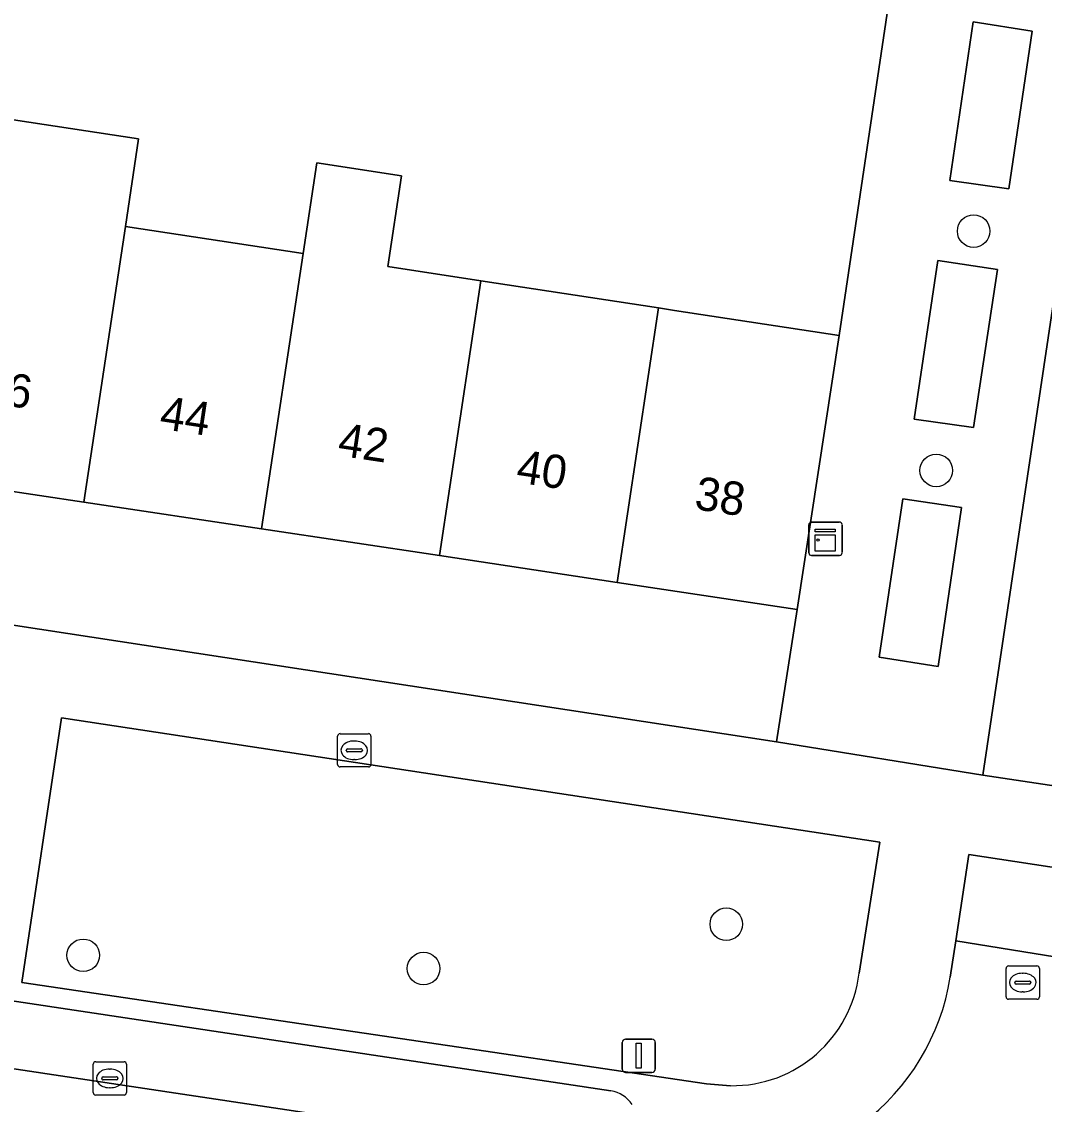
# Model space of a CAD drawing. Extents: x 163008 to 163854, y 382777 to 383982.
# Drawn here: x 163578.61 to 163609.33, y 383213.27 to 383245.8 of the extents above; entities that cross this region are included whole.
import ezdxf

# ---------------------------------------------------------------- set-up
doc = ezdxf.new("R2010")
doc.units = 0
for name, color, linetype in [('IMGEO_Boom', 7, 'Continuous'), ('IMGEO_Brandkraan', 7, 'Continuous'), ('IMGEO_Erf', 7, 'Continuous'), ('IMGEO_Groenvoorziening', 7, 'Continuous'), ('IMGEO_Kast', 7, 'Continuous'), ('IMGEO_Kolk', 7, 'Continuous'), ('IMGEO_Lichtmast', 7, 'Continuous'), ('IMGEO_Muur', 7, 'Continuous'), ('IMGEO_Pand', 7, 'Continuous'), ('IMGEO_Pand_nummerreeks', 7, 'Continuous'), ('IMGEO_Parkeervlak_open', 7, 'Continuous'), ('IMGEO_Rijbaan_lokaal_gesloten', 7, 'Continuous'), ('IMGEO_Rijbaan_lokaal_open', 7, 'Continuous'), ('IMGEO_Rioolput', 7, 'Continuous'), ('IMGEO_Voetpad_open', 7, 'Continuous')]:
    doc.layers.add(name, color=color, linetype=linetype)

msp = doc.modelspace()

# ---------------------------------------------------------------- linework, layer by layer
at = {"layer": 'IMGEO_Boom'}
for centre in [(163607.204, 383239.508), (163606.082, 383232.318), (163599.776, 383218.685), (163580.462, 383217.75), (163590.684, 383217.351)]:
    msp.add_circle(centre, 0.489, dxfattribs=at)
at = {"layer": 'IMGEO_Brandkraan'}
for p, q in [((163588.102, 383223.483), (163588.102, 383224.335)), ((163588.177, 383224.409), (163589.029, 383224.409)), ((163589.103, 383224.335), (163589.103, 383223.483)), ((163588.59, 383224.189), (163588.615, 383224.189)), ((163588.361, 383223.903), (163588.361, 383223.915)), ((163588.799, 383223.866), (163588.401, 383223.866)), ((163588.404, 383223.952), (163588.802, 383223.952)), ((163588.845, 383223.915), (163588.845, 383223.903)), ((163589.029, 383223.409), (163588.177, 383223.409)), ((163588.613, 383223.629), (163588.588, 383223.629))]:
    msp.add_line(p, q, dxfattribs=at)
for points in [[(163588.102, 383223.483), (163588.102, 383224.335)], [(163588.177, 383224.409), (163589.029, 383224.409)], [(163589.103, 383224.335), (163589.103, 383223.483)], [(163589.029, 383223.409), (163588.177, 383223.409)]]:
    msp.add_lwpolyline(points, dxfattribs=at)
for centre, radius, start, end in [((163588.179, 383224.333), 0.0765, 91.552, 178.448), ((163588.179, 383224.333), 0.0765, 91.552, 178.448), ((163589.027, 383224.333), 0.0765, 1.552, 88.448), ((163589.027, 383224.333), 0.0765, 1.552, 88.448), ((163588.401, 383223.912), 0.0403, 85.8775, 175.7526), ((163588.398, 383223.902), 0.0366, 178.938, 274.7102), ((163588.802, 383223.909), 0.043, 264.8664, 352.4533), ((163588.806, 383223.914), 0.0386, 1.7309, 96.639), ((163588.179, 383223.485), 0.0765, 181.552, 268.448), ((163588.179, 383223.485), 0.0765, 181.552, 268.448), ((163589.027, 383223.485), 0.0765, 271.552, 358.448), ((163589.027, 383223.485), 0.0765, 271.552, 358.448)]:
    msp.add_arc(centre, radius, start, end, dxfattribs=at)
for centre, major_axis, ratio, start_param, end_param in [((163588.589, 383223.909), (-0.387, 0.002), 0.722429, 4.712389, 7.853982), ((163588.614, 383223.909), (-0.39, 0.002), 0.717154, 1.570796, 4.712389)]:
    msp.add_ellipse(centre, major_axis=major_axis, ratio=ratio, start_param=start_param, end_param=end_param, dxfattribs=at)
at = {"layer": 'IMGEO_Erf'}
msp.add_lwpolyline([(163555.832, 383249.496), (163554.992, 383243.736), (163559.935, 383242.98), (163560.373, 383242.913), (163565.712, 383242.097), (163571.05, 383241.28), (163576.388, 383240.464), (163576.774, 383243.089), (163582.123, 383242.284), (163581.726, 383239.648), (163587.063, 383238.831), (163587.473, 383241.556), (163590.025, 383241.172), (163589.614, 383238.441), (163592.401, 383238.015), (163597.739, 383237.199), (163598.222, 383237.125), (163603.164, 383236.369), (163604.845, 383247.675)], dxfattribs=at)
msp.add_lwpolyline([(163553.141, 383231.523), (163601.286, 383224.16), (163601.906, 383228.141), (163596.498, 383228.955), (163591.158, 383229.759), (163585.818, 383230.562), (163580.479, 383231.366), (163575.139, 383232.17), (163569.799, 383232.973), (163564.459, 383233.777), (163559.119, 383234.581), (163553.717, 383235.394)], close=True, dxfattribs=at)
at = {"layer": 'IMGEO_Groenvoorziening'}
msp.add_lwpolyline([(163603.762, 383217.217), (163604.384, 383221.146), (163579.809, 383224.886), (163578.619, 383216.935), (163599.182, 383213.891), (163599.899, 383213.833)], dxfattribs=at)
msp.add_arc((163599.96, 383217.661), 3.828, 269.0921, 353.3448, dxfattribs=at)
at = {"layer": 'IMGEO_Kast'}
for p, q in [((163602.252, 383229.838), (163602.252, 383230.679)), ((163602.252, 383230.679), (163602.252, 383229.838)), ((163602.327, 383230.763), (163603.168, 383230.763)), ((163603.168, 383230.763), (163602.327, 383230.763)), ((163603.252, 383230.688), (163603.252, 383229.847)), ((163603.252, 383229.847), (163603.252, 383230.688)), ((163603.177, 383229.763), (163602.336, 383229.763)), ((163602.336, 383229.763), (163603.177, 383229.763))]:
    msp.add_line(p, q, dxfattribs=at)
for points in [[(163602.447, 383230.553), (163603.047, 383230.553), (163603.047, 383230.468), (163602.447, 383230.468), (163602.447, 383230.553)], [(163602.447, 383230.378), (163603.047, 383230.378), (163603.047, 383229.889), (163602.447, 383229.889), (163602.447, 383230.378)]]:
    msp.add_lwpolyline(points, dxfattribs=at)
msp.add_circle((163602.531, 383230.227), 0.0377, dxfattribs=at)
for centre, start, end in [((163602.33, 383230.685), 92.4484, 184.2845), ((163602.33, 383230.685), 92.4484, 184.2845), ((163603.174, 383230.685), 2.4484, 94.2845), ((163603.174, 383230.685), 2.4484, 94.2845), ((163602.33, 383229.841), 182.4484, 274.2845), ((163602.33, 383229.841), 182.4484, 274.2845), ((163603.174, 383229.841), 272.4484, 4.2845), ((163603.174, 383229.841), 272.4484, 4.2845)]:
    msp.add_arc(centre, 0.0779, start, end, dxfattribs=at)
at = {"layer": 'IMGEO_Kolk'}
for p, q in [((163580.76, 383213.627), (163580.76, 383214.479)), ((163580.835, 383214.553), (163581.687, 383214.553)), ((163581.248, 383214.333), (163581.273, 383214.333)), ((163581.761, 383214.479), (163581.761, 383213.627)), ((163581.019, 383214.047), (163581.019, 383214.059)), ((163581.457, 383214.01), (163581.059, 383214.01)), ((163581.062, 383214.096), (163581.46, 383214.096)), ((163581.503, 383214.059), (163581.503, 383214.047)), ((163581.271, 383213.773), (163581.246, 383213.773)), ((163581.687, 383213.553), (163580.835, 383213.553))]:
    msp.add_line(p, q, dxfattribs=at)
for points in [[(163580.76, 383213.627), (163580.76, 383214.479)], [(163580.835, 383214.553), (163581.687, 383214.553)], [(163581.761, 383214.479), (163581.761, 383213.627)], [(163581.687, 383213.553), (163580.835, 383213.553)]]:
    msp.add_lwpolyline(points, dxfattribs=at)
for centre, radius, start, end in [((163580.837, 383214.477), 0.0765, 91.552, 178.448), ((163580.837, 383214.477), 0.0765, 91.552, 178.448), ((163581.685, 383214.477), 0.0765, 1.552, 88.448), ((163581.685, 383214.477), 0.0765, 1.552, 88.448), ((163581.059, 383214.056), 0.0403, 85.8775, 175.7526), ((163581.056, 383214.046), 0.0366, 178.938, 274.7102), ((163581.46, 383214.053), 0.043, 264.8664, 352.4533), ((163581.464, 383214.058), 0.0386, 1.7309, 96.639), ((163580.837, 383213.629), 0.0765, 181.552, 268.448), ((163580.837, 383213.629), 0.0765, 181.552, 268.448), ((163581.685, 383213.629), 0.0765, 271.552, 358.448), ((163581.685, 383213.629), 0.0765, 271.552, 358.448)]:
    msp.add_arc(centre, radius, start, end, dxfattribs=at)
for centre, major_axis, ratio, start_param, end_param in [((163581.247, 383214.053), (-0.387, 0.002), 0.722429, 4.712389, 7.853982), ((163581.272, 383214.053), (-0.39, 0.002), 0.717154, 1.570796, 4.712389)]:
    msp.add_ellipse(centre, major_axis=major_axis, ratio=ratio, start_param=start_param, end_param=end_param, dxfattribs=at)
at = {"layer": 'IMGEO_Lichtmast'}
for p, q in [((163596.752, 383215.234), (163597.542, 383215.234)), ((163597.542, 383215.234), (163596.752, 383215.234)), ((163596.652, 383214.334), (163596.652, 383215.134)), ((163596.652, 383215.134), (163596.652, 383214.334)), ((163597.642, 383215.134), (163597.642, 383214.334)), ((163597.642, 383214.334), (163597.642, 383215.134)), ((163597.542, 383214.234), (163596.752, 383214.234)), ((163596.752, 383214.234), (163597.542, 383214.234))]:
    msp.add_line(p, q, dxfattribs=at)
msp.add_lwpolyline([(163597.072, 383215.109), (163597.222, 383215.109), (163597.222, 383214.359), (163597.072, 383214.359), (163597.072, 383215.109)], dxfattribs=at)
for centre, start, end in [((163596.752, 383215.134), 90, 180), ((163596.752, 383215.134), 90, 180), ((163597.542, 383215.134), 0, 90), ((163597.542, 383215.134), 360, 90), ((163596.752, 383214.334), 180, 270), ((163596.752, 383214.334), 180, 270), ((163597.542, 383214.334), 270, 0), ((163597.542, 383214.334), 270, 0)]:
    msp.add_arc(centre, 0.1, start, end, dxfattribs=at)
at = {"layer": 'IMGEO_Muur'}
msp.add_lwpolyline([(163603.164, 383236.369), (163604.845, 383247.675)], dxfattribs=at)
at = {"layer": 'IMGEO_Pand'}
for points in [[(163581.726, 383239.648), (163582.123, 383242.284), (163576.774, 383243.089), (163576.388, 383240.464), (163575.139, 383232.17), (163580.479, 383231.366)], [(163587.063, 383238.831), (163585.818, 383230.562), (163591.158, 383229.759), (163592.401, 383238.015), (163589.614, 383238.441), (163590.025, 383241.172), (163587.473, 383241.556)], [(163587.063, 383238.831), (163581.726, 383239.648), (163580.479, 383231.366), (163585.818, 383230.562)], [(163596.498, 383228.955), (163597.739, 383237.199), (163592.401, 383238.015), (163591.158, 383229.759)], [(163596.498, 383228.955), (163601.906, 383228.141), (163603.164, 383236.369), (163598.222, 383237.125), (163597.739, 383237.199)]]:
    msp.add_lwpolyline(points, close=True, dxfattribs=at)
at = {"layer": 'IMGEO_Parkeervlak_open'}
for points in [[(163608.265, 383240.776), (163608.962, 383245.518), (163607.192, 383245.792), (163606.49, 383241.023)], [(163607.195, 383233.61), (163607.921, 383238.358), (163606.126, 383238.625), (163605.417, 383233.862)], [(163606.139, 383226.43), (163606.843, 383231.208), (163605.075, 383231.468), (163604.365, 383226.703)]]:
    msp.add_lwpolyline(points, close=True, dxfattribs=at)
for points in [[(163596.308, 383213.676), (163554.672, 383219.939)], [(163551.582, 383218.367), (163599.104, 383211.221)]]:
    msp.add_lwpolyline(points, dxfattribs=at)
msp.add_arc((163596.173, 383212.752), 0.933, 33.9028, 81.701, dxfattribs=at)
at = {"layer": 'IMGEO_Rijbaan_lokaal_gesloten'}
msp.add_lwpolyline([(163551.317, 383216.605), (163599.147, 383209.408), (163599.431, 383211.199), (163599.104, 383211.221), (163551.582, 383218.367)], close=True, dxfattribs=at)
at = {"layer": 'IMGEO_Rijbaan_lokaal_open'}
msp.add_lwpolyline([(163610.88, 383222.652), (163614.476, 383246.512), (163611.042, 383247.039), (163607.483, 383223.163)], close=True, dxfattribs=at)
msp.add_lwpolyline([(163609.834, 383216.499), (163610.014, 383217.649), (163606.665, 383218.189), (163606.501, 383217.095)], dxfattribs=at)
msp.add_arc((163599.715, 383218.176), 6.872, 306.9552, 350.9455, dxfattribs=at)
at = {"layer": 'IMGEO_Rioolput'}
for p, q in [((163608.178, 383216.505), (163608.178, 383217.357)), ((163608.253, 383217.431), (163609.105, 383217.431)), ((163608.666, 383217.211), (163608.691, 383217.211)), ((163609.179, 383217.357), (163609.179, 383216.505)), ((163608.437, 383216.925), (163608.437, 383216.937)), ((163608.875, 383216.888), (163608.477, 383216.888)), ((163608.48, 383216.974), (163608.878, 383216.974)), ((163608.921, 383216.937), (163608.921, 383216.925)), ((163608.689, 383216.651), (163608.664, 383216.651)), ((163609.105, 383216.431), (163608.253, 383216.431))]:
    msp.add_line(p, q, dxfattribs=at)
for points in [[(163608.178, 383216.505), (163608.178, 383217.357)], [(163608.253, 383217.431), (163609.105, 383217.431)], [(163609.179, 383217.357), (163609.179, 383216.505)], [(163609.105, 383216.431), (163608.253, 383216.431)]]:
    msp.add_lwpolyline(points, dxfattribs=at)
for centre, radius, start, end in [((163608.255, 383217.355), 0.0765, 91.552, 178.448), ((163608.255, 383217.355), 0.0765, 91.552, 178.448), ((163609.103, 383217.355), 0.0765, 1.552, 88.448), ((163609.103, 383217.355), 0.0765, 1.552, 88.448), ((163608.477, 383216.934), 0.0403, 85.8775, 175.7526), ((163608.474, 383216.924), 0.0366, 178.938, 274.7102), ((163608.878, 383216.931), 0.043, 264.8664, 352.4533), ((163608.882, 383216.936), 0.0386, 1.7309, 96.639), ((163608.255, 383216.507), 0.0765, 181.552, 268.448), ((163608.255, 383216.507), 0.0765, 181.552, 268.448), ((163609.103, 383216.507), 0.0765, 271.552, 358.448), ((163609.103, 383216.507), 0.0765, 271.552, 358.448)]:
    msp.add_arc(centre, radius, start, end, dxfattribs=at)
for centre, major_axis, ratio, start_param, end_param in [((163608.665, 383216.931), (-0.387, 0.002), 0.722429, 4.712389, 7.853982), ((163608.69, 383216.931), (-0.39, 0.002), 0.717154, 1.570796, 4.712389)]:
    msp.add_ellipse(centre, major_axis=major_axis, ratio=ratio, start_param=start_param, end_param=end_param, dxfattribs=at)
at = {"layer": 'IMGEO_Voetpad_open'}
for points in [[(163618.941, 383233.649), (163620.614, 383244.998), (163620.668, 383245.357), (163620.284, 383245.414), (163620.803, 383248.742), (163618.346, 383249.06), (163614.854, 383249.541), (163611.826, 383250), (163611.443, 383250.058), (163608.303, 383250.604), (163605.388, 383251.086), (163605.18, 383250), (163604.845, 383247.675), (163603.164, 383236.369), (163601.906, 383228.141), (163601.286, 383224.16), (163607.483, 383223.163), (163611.042, 383247.039), (163614.476, 383246.512), (163610.88, 383222.652), (163617.111, 383221.572), (163617.75, 383225.735)], [(163608.265, 383240.776), (163606.49, 383241.023), (163607.192, 383245.792), (163608.962, 383245.518)], [(163607.195, 383233.61), (163605.417, 383233.862), (163606.126, 383238.625), (163607.921, 383238.358)], [(163606.139, 383226.43), (163604.365, 383226.703), (163605.075, 383231.468), (163606.843, 383231.208)], [(163610.417, 383220.269), (163607.06, 383220.78), (163606.665, 383218.189), (163610.014, 383217.649)]]:
    msp.add_lwpolyline(points, close=True, dxfattribs=at)
for points in [[(163610.88, 383222.652), (163607.483, 383223.163), (163601.286, 383224.16), (163553.141, 383231.523), (163553.112, 383231.333), (163546.124, 383232.387), (163542.594, 383232.919), (163542.114, 383230.548), (163545.619, 383230.024), (163544.84, 383224.686)], [(163599.899, 383213.833), (163599.182, 383213.891), (163578.619, 383216.935), (163579.809, 383224.886), (163604.384, 383221.146)], [(163606.501, 383217.095), (163606.665, 383218.189), (163607.06, 383220.78), (163610.417, 383220.269), (163610.88, 383222.652)], [(163604.384, 383221.146), (163603.762, 383217.217)], [(163554.672, 383219.939), (163596.308, 383213.676)]]:
    msp.add_lwpolyline(points, dxfattribs=at)
for centre, radius, start, end in [((163599.96, 383217.661), 3.828, 269.0921, 353.3448), ((163599.715, 383218.176), 6.872, 306.9552, 350.9455), ((163596.173, 383212.752), 0.933, 33.9028, 81.701)]:
    msp.add_arc(centre, radius, start, end, dxfattribs=at)

# ---------------------------------------------------------------- texts
at = {"layer": 'IMGEO_Pand_nummerreeks'}
for s, rotation, p in [('46', 351.44, (163577.37, 383234.383)), ('44', 351.4406, (163582.723, 383233.576)), ('42', 351.4406, (163588.075, 383232.77)), ('40', 351.4406, (163593.435, 383231.964)), ('38', 351.4406, (163598.789, 383231.158))]:
    msp.add_text(s, height=1, rotation=rotation, dxfattribs=at).set_placement(p)

doc.saveas('drawing.dxf')
